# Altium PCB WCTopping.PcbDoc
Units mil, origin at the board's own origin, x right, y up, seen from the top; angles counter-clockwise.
Board outline 6000 x 4000 mil, 2 copper layers (Top Layer, Bottom Layer); 59 components, 76 nets, 281 pads, 0 vias.
Unrouted connection lines stored in the file: 177.
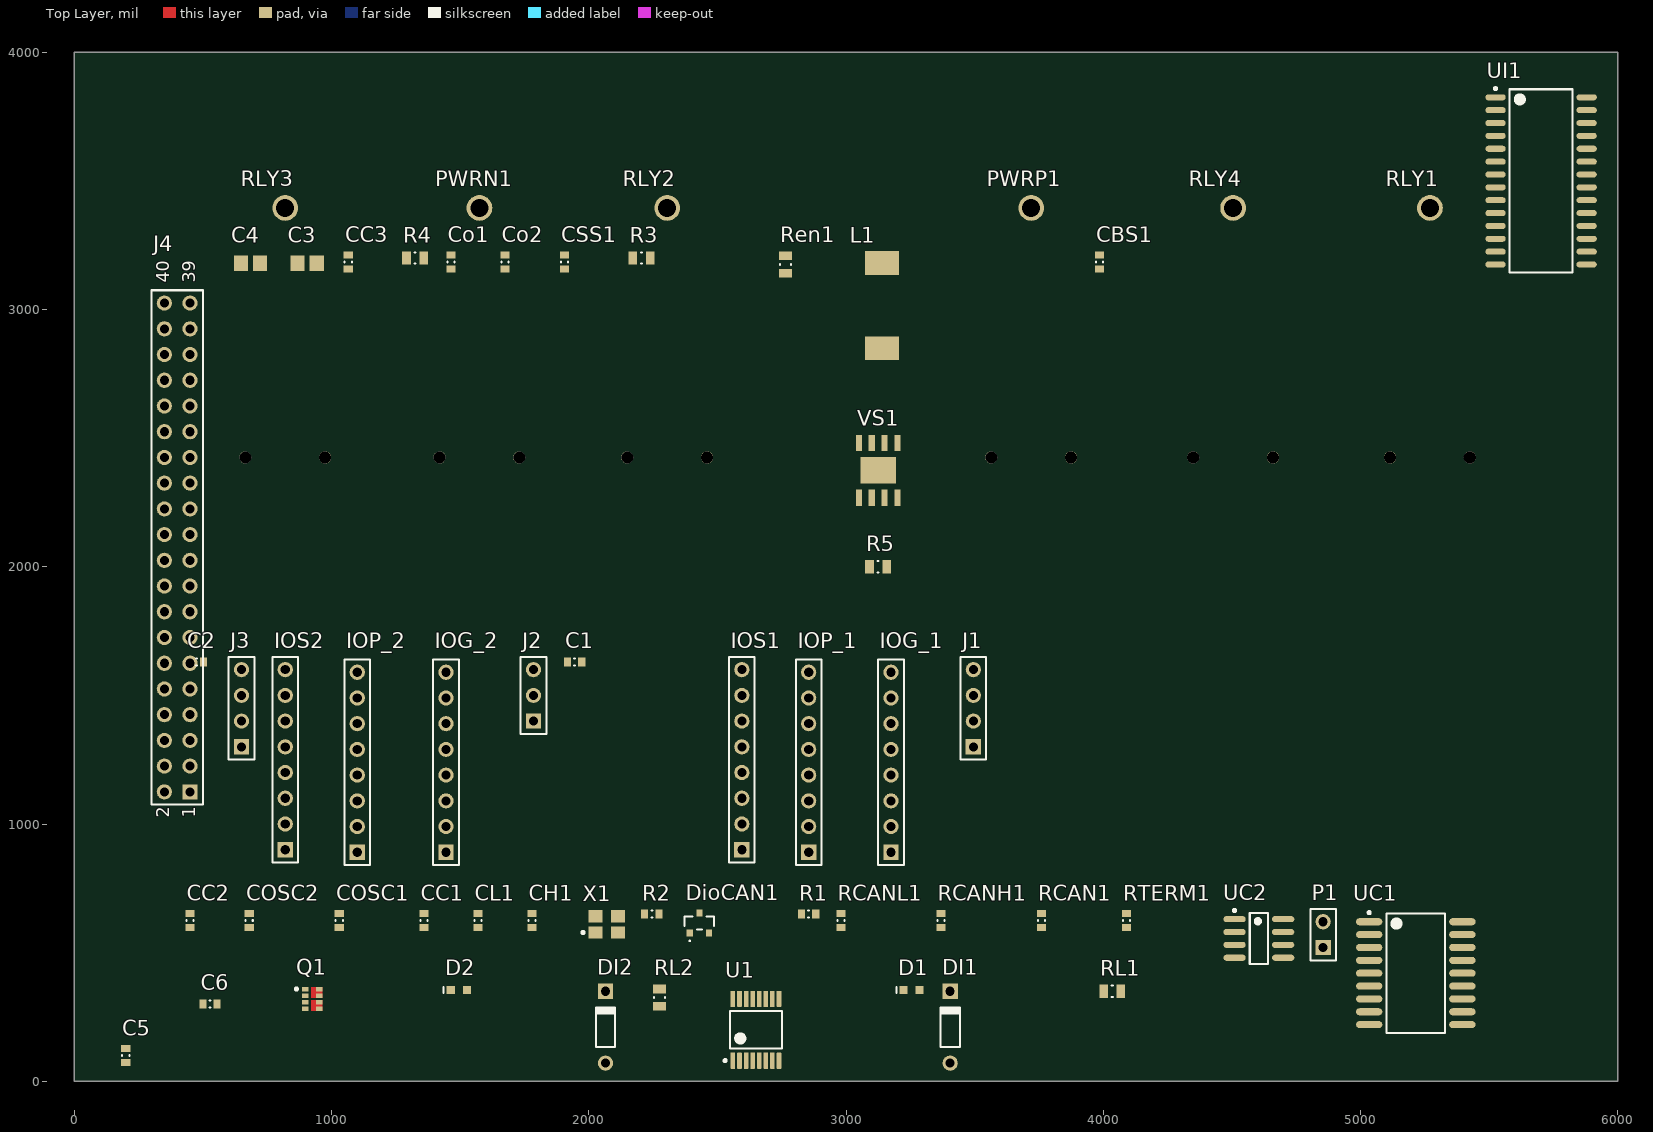
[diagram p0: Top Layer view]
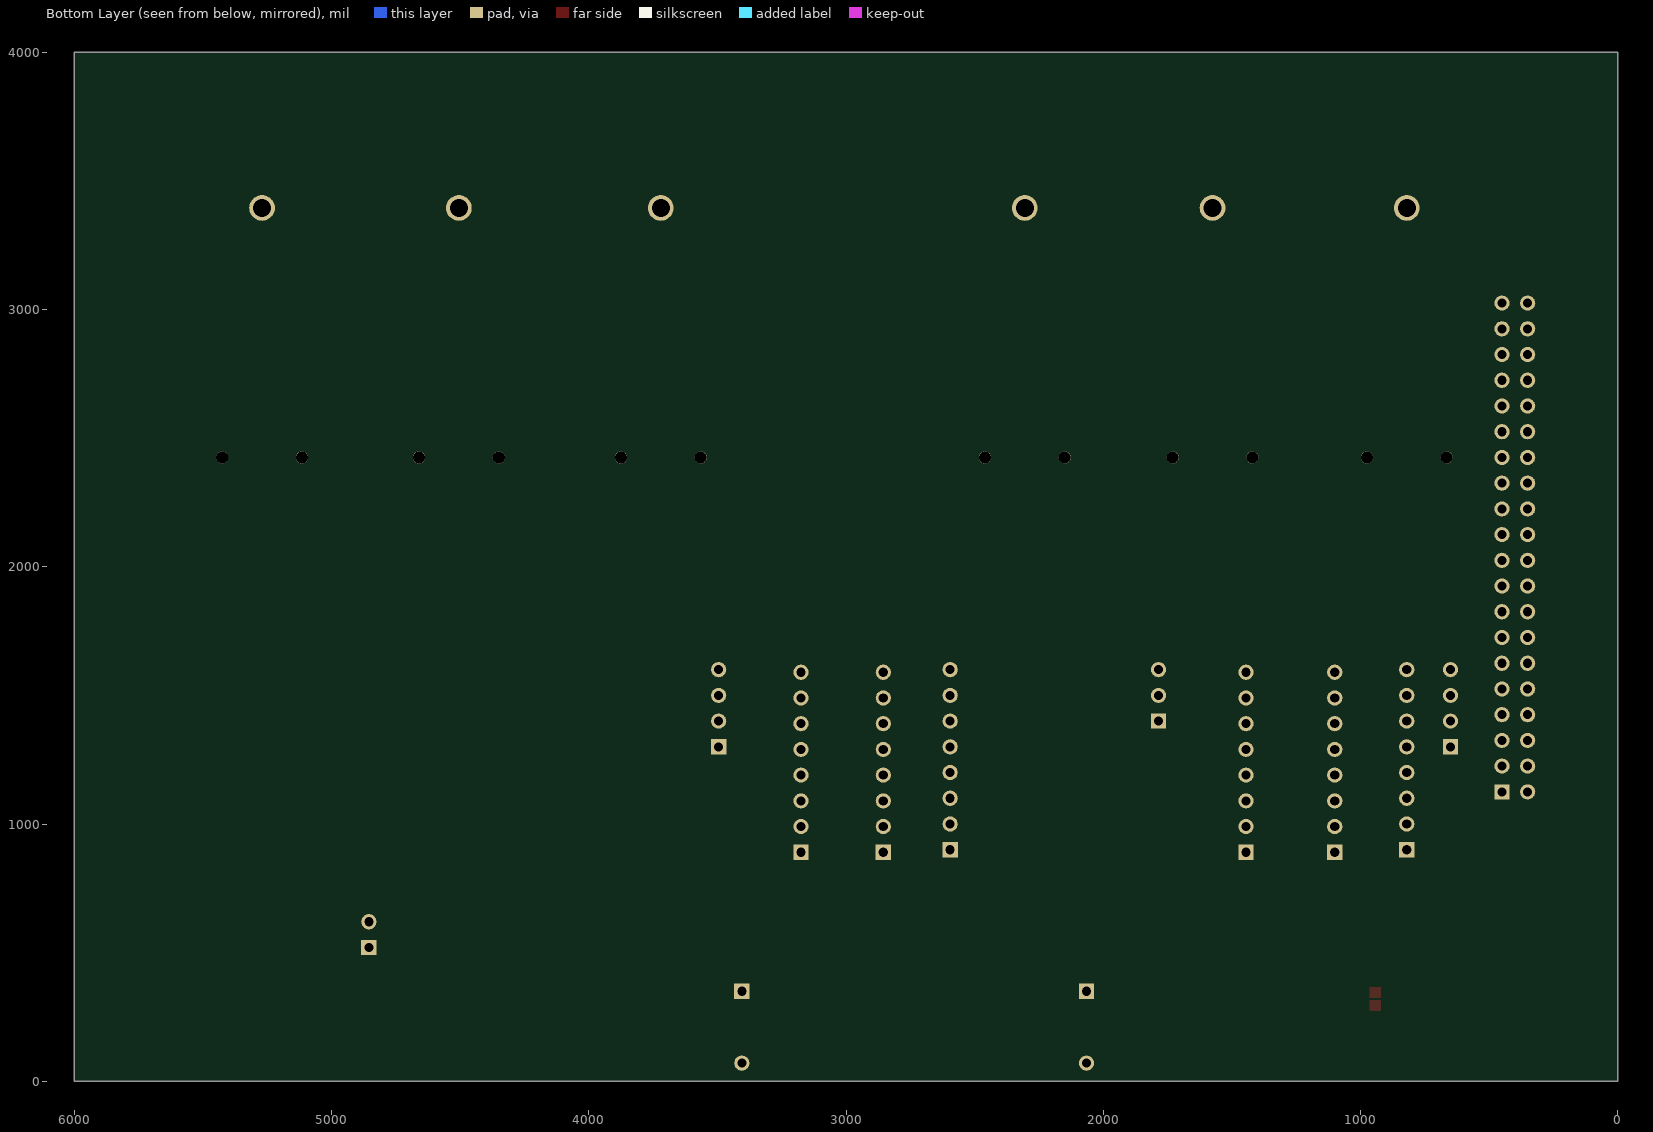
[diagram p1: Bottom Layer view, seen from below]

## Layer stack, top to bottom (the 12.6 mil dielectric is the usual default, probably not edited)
Top Solder: solder mask 0.4, Solder Resist, Dk 3.5
Top Layer: signal copper 1.4
Dielectric 1: dielectric 12.6, FR-4, Dk 4.8
Bottom Layer: signal copper 1.4
Bottom Solder: solder mask 0.4, Solder Resist, Dk 3.5

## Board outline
0,0 6000,0 6000,4000 0,4000

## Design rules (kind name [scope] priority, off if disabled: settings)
Clearance [All] p1: gap=10 ignorepadtopadclearanceinfootprint=FALSE except(0: Arc-Hole Track-Hole SMDPad-Hole THPad-Hole Via-Hole Fill-Hole Poly-Hole Region-Hole Text-Hole)
PolygonConnect [All] p1: connectstyle=Relief reliefconductorwidth=10 reliefentries=4 polygonreliefangle="90 Angle" airgapwidth=10
RoutingVias [All] p1: holewidth=28 width=50 viastyle="Through Hole" minholewidth=28 minwidth=50 maxholewidth=28 maxwidth=50
SolderMaskExpansion [All] p1: expansion=4
Width [All] p1: maxlimit=10 minlimit=10 preferedwidth=10
30 further rules are at their usual default settings.

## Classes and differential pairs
component class CAN_Interface: CC1 CC2 CH1 CL1 COSC1 COSC2 DioCAN1 P1 R1 R2 RCAN1 RCANH1 RCANL1 RTERM1 UC1 UC2 X1
component class Digital_IO: C1 C2 IOG_1 IOG_2 IOP_1 IOP_2 IOS1 IOS2 J1 J2 J3 UI1
component class "Power Supply": C3 C4 CBS1 CC3 Co1 Co2 CSS1 L1 PWRN1 PWRP1 R3 R4 R5 Ren1 VS1
component class Processor_Interface: C5 C6 J4
component class Relay_IO: D1 D2 DI1 DI2 Q1 RL1 RL2 RLY1 RLY2 RLY3 RLY4 U1
net class RELAY[1..2]: RELAY1 RELAY2

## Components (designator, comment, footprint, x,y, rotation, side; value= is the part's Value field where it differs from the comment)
C1 "100nF 50V" 0603C_L 1945,1630 r0 top
C2 "100nF 50V" 0603C_L 475,1630 r0 top
C3 "10µF" CAPC2013X135X45ML10T25 905,3180 r0 top
C4 "10µF" CAPC2013X135X45ML10T25 685,3180 r0 top
C5 "100nF 50V" 0603C_L 200,100 r270 top
C6 "100nF 50V" 0603C_L 527.56,300 r0 top
CBS1 "10000pF 50V 0603" 0603C_L 3985,3185 r90 top
CC1 "0.1uF" 0603C_L 1360,625 r90 top
CC2 "0.1uF" 0603C_L 450,625 r90 top
CC3 "3900pF" 0603C_L 1065,3185 r90 top
CH1 "560pF 25V 0603" 0603C_L 1780,625 r90 top
CL1 "560pF 25V 0603" 0603C_L 1570,625 r90 top
Co1 "22uF" 0603C_L 1465,3185 r90 top
Co2 "22uF" 0603C_L 1675,3185 r90 top
COSC1 "22pF" 0603C_L 1030,625 r90 top
COSC2 "22pF" 0603C_L 680,625 r90 top
CSS1 "100nF 50V" 0603C_L 1905,3185 r90 top
D1 "LED Red" 0603_A 3255,355 r0 top
D2 "LED Red" 0603_A 1495,355 r0 top
DI1 "100V 1A Fast Diode" DO-35 3405,210 r90 top
DI2 "100V 1A Fast Diode" DO-35 2065,210 r90 top
DioCAN1 "100V 1A Fast Diode" SOT23 2430,615 r90 top
IOG_1 "Header 8" HDR1X8 3175,890 r90 top
IOG_2 "Header 8" HDR1X8 1445,890 r90 top
IOP_1 "Header 8" HDR1X8 2855,890 r90 top
IOP_2 "Header 8" HDR1X8 1100,890 r90 top
IOS1 "Header 8" HDR1X8 2595,900 r90 top
IOS2 "Header 8" HDR1X8 820,900 r90 top
J1 "Header 4" HDR1X4 3495,1300 r90 top
J2 "Header 3" HDR1X3 1785,1400 r90 top
J3 "Header 4" HDR1X4 650,1300 r90 top
J4 "Header 20X2" HDR2X20 450,1125 r90 top
L1 "10uH" IND_1 3140,3015 r90 top
P1 "Header 2" HDR1X2 4855,520 r90 top
PWRN1 "BLK_PCB_RHT" Anderson_BLK_RHT_BOT 1575,3395 r90 top
PWRP1 "RED_PCB_RHT" Anderson_Red_RHT_BOT 3720,3395 r90 top
Q1 "NTHD4508NT1" ONSC-CHIPFET-8-1206A-03_S2_V 925,320 r0 top
R1 "10K 0603" 0603_L 2855,650 r0 top
R2 "22K" 0603_L 2245,650 r0 top
R3 "#NAME?" 0805_L 2205,3200 r0 top
R4 "10 kOhms" 0805_L 1325,3200 r0 top
R5 "6.8 kOhms" 0805_L 3125,2000 r180 top
RCAN1 "4.7K" 0603_L 3760,625 r90 top
RCANH1 "100" 0603_L 3370,625 r90 top
RCANL1 "100" 0603_L 2980,625 r90 top
Ren1 "100K 0805" 0805_L 2765,3175 r90 top
RL1 "1K 0805" 0805_L 4035,350 r0 top
RL2 "1K 0805" 0805_L 2275,325 r90 top
RLY1 "Anderson-1Pin RED_PCB_RHT" Anderson_Red_RHT_BOT 5270,3395 r90 top
RLY2 "Anderson-1Pin BLK_PCB_RHT" Anderson_BLK_RHT_BOT 2305,3395 r90 top
RLY3 "Anderson-1Pin RED_PCB_RHT" Anderson_Red_RHT_BOT 820,3395 r90 top
RLY4 "Anderson-1Pin BLK_PCB_RHT" Anderson_BLK_RHT_BOT 4505,3395 r90 top
RTERM1 "130ohm 0603" 0603_L 4090,625 r90 top
U1 "CD40109BPW" PW0016A_M 2650,200 r90 top
UC1 "MCP2515-E/SO" SOIC-SO18_M 5215,420 r0 top
UC2 "MCP2551-E/SN" SOIC-SN8_N 4605,555 r0 top
UI1 "MCP23S17T-E/SO" SOIC-SO28_L 5702.17,3500 r0 top
VS1 "MP2307" SOIC8N_EXP 3125,2375 r0 top
X1 "21C00047-16.000MHz" ITTI-21C00047-16.000MHz-4_V 2070,610 r0 top

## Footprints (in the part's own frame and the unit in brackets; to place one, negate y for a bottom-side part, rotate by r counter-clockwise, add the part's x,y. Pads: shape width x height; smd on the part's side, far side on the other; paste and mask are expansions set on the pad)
0603_A [mm] "Chip LED, 2-Leads, Body 1.6x0.8mm, IPC Medium Density"
  rect 0.8x0.8 smd: 1(-0.8,0) 2(0.8,0)
  silkscreen extent -1.5,-0.3 -1.5,0.3, body extent -0.8,-0.4 0.8,0.4, height 0.7
0603_L [mm]
  rect 0.7x0.9 smd: 1(-0.7,0) 2(0.7,0)
  silkscreen extent -0.05,-0.35 0.05,0.35, body extent -0.85,-0.47 0.85,0.47, height 0.6
0603C_L [mm]
  rect 0.7x0.9 smd: 1(-0.7,0) 2(0.7,0)
  silkscreen extent -0.05,-0.35 0.05,0.35, body extent -0.87,-0.47 0.88,0.48, height 1
0805_L [mm]
  rect 0.85x1.3 smd: 1(-0.85,0) 2(0.85,0)
  silkscreen extent -0.05,-0.55 0.05,0.55, body extent -1.1,-0.67 1.1,0.68, height 0.7
Anderson_BLK_RHT_BOT [mil]
  round 100 hole 70: 1(0,0)
  round 47 hole 47 unplated: MH(-970,-155) MH(-970,155)
  body extent -1360,-155 25,155, height 310
Anderson_Red_RHT_BOT [mil]
  round 100 hole 70: 1(0,0)
  round 47 hole 47 unplated: MH(-970,-155) MH(-970,155)
  body extent -1360,-155 25,155, height 310
CAPC2013X135X45ML10T25 [mm] "Chip Capacitor, 2-Leads, Body 2.00x1.25mm, IPC Low Density"
  rect 1.4x1.5 smd: 1(-0.95,0) 2(0.95,0)
  body extent -1.05,-0.67 1.05,0.67, height 1.35
DO-35 [mm] "Diode, Axial; Body 3.8 x 1.9 mm (LxDia. max), Lead Dia. 0.53 mm (max)"
  round 1.5 hole 0.9: 1(-3.55,0)
  rect 1.5x1.5 hole 0.9: 2(3.55,0)
  silkscreen extent -1.95,-0.95 2.05,0.95
HDR1X2 [mm] "Connector; Header; 2 Position"
  rect 1.5x1.5 hole 0.9: 1(0,0)
  round 1.5 hole 0.9: 2(2.54,0)
  silkscreen extent -1.27,-1.27 3.81,1.27
HDR1X3 [mm] "Connector; Header; 3 Position"
  rect 1.5x1.5 hole 0.9: 1(0,0)
  round 1.5 hole 0.9: 2(2.54,0) 3(5.08,0)
  silkscreen extent -1.27,-1.27 6.35,1.27
HDR1X4 [mm] "Connector; Header; 4 Position"
  rect 1.5x1.5 hole 0.9: 1(0,0)
  round 1.5 hole 0.9: 2(2.54,0) 3(5.08,0) 4(7.62,0)
  silkscreen extent -1.27,-1.27 8.89,1.27
HDR1X8 [mm] "Connector; Header; 8 Position"
  rect 1.5x1.5 hole 0.9: 1(0,0)
  round 1.5 hole 0.9: 2(2.54,0) 3(5.08,0) 4(7.62,0) 5(10.16,0) 6(12.7,0) 7(15.24,0) 8(17.78,0)
  silkscreen extent -1.27,-1.27 19.05,1.27
HDR2X20 [mm] "Connector; Header; 20x2 Position"
  rect 1.5x1.5 hole 0.9: 1(0,0)
  round 1.5 hole 0.9: 2(0,2.54) 3(2.54,0) 4(2.54,2.54) 5(5.08,0) 6(5.08,2.54) 7(7.62,0) 8(7.62,2.54) 9(10.16,0) 10(10.16,2.54) 11(12.7,0) 12(12.7,2.54) 13(15.24,0) 14(15.24,2.54) 15(17.78,0) 16(17.78,2.54) 17(20.32,0) 18(20.32,2.54) 19(22.86,0) 20(22.86,2.54) 21(25.4,0) 22(25.4,2.54) 23(27.94,0) 24(27.94,2.54) 25(30.48,0) 26(30.48,2.54) 27(33.02,0) 28(33.02,2.54) 29(35.56,0) 30(35.56,2.54) 31(38.1,0) 32(38.1,2.54) 33(40.64,0) 34(40.64,2.54) 35(43.18,0) 36(43.18,2.54) 37(45.72,0) 38(45.72,2.54) 39(48.26,0) 40(48.26,2.54)
  silkscreen extent -1.27,-1.27 49.53,3.81
IND_1 [mil]
  rect 92.52x134 smd: 1(-165.5,0) 2(165.5,0)
  body extent -142,-127 142,135, height 118
ITTI-21C00047-16.000MHz-4_V [mm] "Hand Drawn, 4-Leads, Body 3.2x2.5 mm"
  rect 1.4x1.2 smd: 1(-1.1,-0.8) 2(1.1,-0.8) 3(1.1,0.8) 4(-1.1,0.8)
  silkscreen extent -2.47,-0.92 -2.23,-0.68, body extent -1.6,-1.25 1.6,1.25, height 0.9
ONSC-CHIPFET-8-1206A-03_S2_V [mil] "SON, 8-Leads, Body 3.025x1.625mm, Pitch 0.635mm"
  rect 25.98x17.99 smd: 1(-27.01,37.5) 2(-27.01,12.5) 3(-27.01,-12.5) 4(-27.01,-37.5) 5(27.01,-37.5) 6(27.01,-12.5) 7(27.01,12.5) 8(27.01,37.5)
  Top Layer region: -4.02,3.5 40,3.5 40,46.5 -4.02,46.5
  Top Layer region: -4.02,-46.5 40,-46.5 40,-3.5 -4.02,-3.5
  silkscreen extent -67,33 -57,43, body extent -32,-60 32,60, height 43
PW0016A_M [mm] "SOP, 16-Leads, Body 5.1x4.5mm, Pitch 0.65mm, IPC Low Density"
  rrect22% 1.6x0.45 smd: 1(-3.05,2.275) 2(-3.05,1.625) 3(-3.05,0.975) 4(-3.05,0.325) 5(-3.05,-0.325) 6(-3.05,-0.975) 7(-3.05,-1.625) 8(-3.05,-2.275) 9(3.05,-2.275) 10(3.05,-1.625) 11(3.05,-0.975) 12(3.05,-0.325) 13(3.05,0.325) 14(3.05,0.975) 15(3.05,1.625) 16(3.05,2.275)
  silkscreen extent -3.17,-2.55 1.85,3.17, body extent -3.21,-2.5 3.21,2.5, height 1
SOIC8N_EXP [mil]
  rect 24x63 smd: 1(-75,-106.5) 2(-25,-106.5) 3(25,-106.5) 4(75,-106.5) 5(75,106.5) 6(25,106.5) 7(-25,106.5) 8(-75,106.5)
  rect 138x103 smd: EP(0,0)
SOIC-SN8_N [mm] "SOIC, 8-Leads, Body 4.9x3.9mm, Pitch 1.27mm, IPC Medium Density"
  oval 2.2x0.6 smd: 1(-2.4,1.905) 2(-2.4,0.635) 3(-2.4,-0.635) 4(-2.4,-1.905) 5(2.4,-1.905) 6(2.4,-0.635) 7(2.4,0.635) 8(2.4,1.905)
  silkscreen extent -2.52,-2.5 0.9,2.88, body extent -2,-2.5 2,2.5, height 1.75
SOIC-SO18_M [mm] "SOIC, 18-Leads, Body 11.6x7.5mm, Pitch 1.27mm, IPC Low Density"
  oval 2.6x0.7 smd: 1(-4.6,5.08) 2(-4.6,3.81) 3(-4.6,2.54) 4(-4.6,1.27) 5(-4.6,0) 6(-4.6,-1.27) 7(-4.6,-2.54) 8(-4.6,-3.81) 9(-4.6,-5.08) 10(4.6,-5.08) 11(4.6,-3.81) 12(4.6,-2.54) 13(4.6,-1.27) 14(4.6,0) 15(4.6,1.27) 16(4.6,2.54) 17(4.6,3.81) 18(4.6,5.08)
  silkscreen extent -4.72,-5.9 2.9,6.1, body extent -3.8,-5.87 3.8,5.87, height 2.65
SOIC-SO28_L [mm] "SOIC, 28-Leads, Body 17.9x7.5mm, Pitch 1.27mm, IPC High Density"
  oval 2x0.6 smd: 1(-4.5,8.255) 2(-4.5,6.985) 3(-4.5,5.715) 4(-4.5,4.445) 5(-4.5,3.175) 6(-4.5,1.905) 7(-4.5,0.635) 8(-4.5,-0.635) 9(-4.5,-1.905) 10(-4.5,-3.175) 11(-4.5,-4.445) 12(-4.5,-5.715) 13(-4.5,-6.985) 14(-4.5,-8.255) 15(4.5,-8.255) 16(4.5,-6.985) 17(4.5,-5.715) 18(4.5,-4.445) 19(4.5,-3.175) 20(4.5,-1.905) 21(4.5,-0.635) 22(4.5,0.635) 23(4.5,1.905) 24(4.5,3.175) 25(4.5,4.445) 26(4.5,5.715) 27(4.5,6.985) 28(4.5,8.255)
  silkscreen extent -4.62,-9.05 3.1,9.23, body extent -3.8,-9.05 3.8,9.05, height 2.65
SOT23 [mm]
  rect 0.7x0.6 smd paste-0.05: 1(-1,0.95) 2(-1,-0.95) 3(1,0)
  silkscreen extent -1.79,-1.45 0.65,1.45, body extent -1.3,-1.5 1.3,1.5, height 1.1

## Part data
C1 C2 C5 C6 CSS1: library part Cap100nF_50V_0603, Capacitance=0.10µF, Manufacturer=Yageo, Manufacturer Part Number=CC0603ZRY5V9BB104, Operating Temperature="-30°C ~ 85°C", Package / Case="0603 (1608 Metric)", Ratings=-, Supplier Part Number 1=311-1343-1-ND, Temperature Coefficient="Y5V (F)", Tolerance="-20%, +80%", Voltage - Rated=50V
C3 C4: library part CMP-2007-03541-1, Manufacturer=Murata, Manufacturer Part Number=GRM21BR61E106KA73L, Operating Temperature="-55°C ~ 85°C", Package / Case="0805 (2012 Metric)", Ratings=-, Standard Package=1, Supplier Part Number 1=490-5523-1-ND, Temperature Coefficient=X5R, Tolerance=±10%, Voltage - Rated=25V
CBS1: library part Cap10000pF_50V_0603, Capacitance=10000pF, Manufacturer=Yageo, Manufacturer Part Number=CC0603KRX7R9BB103, Operating Temperature="-55°C ~ 125°C", Package / Case="0603 (1608 Metric)", Ratings=-, Standard Package=1, Supplier Part Number 1=311-1085-1-ND, Temperature Coefficient=X7R, Tolerance=±10%, Voltage - Rated=50V
CC1 CC2: library part Cap10uF_25V_0603
CC3: library part Cap_0603_1, Case Style="Ceramic Chip", Manufacturer=Murata, Manufacturer Part Number=GRM188R71E392KA01D, Operating Temp Range="-55C to 125C", Package / Case=0603, Supplier Part Number 1=490-11525-1-ND, Temp Coeff (Dielectric)=X7R, Tolerance (+ or -)=10%, Voltage=25VDC
CH1 CL1: library part Cap10uF_25V_0603, Capacitance=10µF, Manufacturer="Taiyo Yuden", Manufacturer Part Number=TMK316F106ZL-T, Operating Temperature="-30°C ~ 85°C", Package / Case="1206 (3216 Metric)", Ratings=-, Standard Package=1, Supplier Part Number 1=587-1353-1-ND, Temperature Coefficient="Y5V (F)", Tolerance="-20%, +80%", Voltage - Rated=25V
Co1 Co2: library part Cap_0603_1, Case Style="Ceramic Chip", Manufacturer=Murata, Manufacturer Part Number=GRM188R60J226MEA0D, Operating Temp Range="-55C to 125C", Package / Case=0603, Supplier Part Number 1=490-7611-1-ND, Temp Coeff (Dielectric)=X5R, Tolerance (+ or -)=20%, Voltage=6.3VDC
COSC1 COSC2: library part Cap100nF_50V_0603, Capacitance=22, Case/Package=0603, Case Code (Metric)=1608, Manufacturer=Murata, Manufacturer Part Number=GRM1885C1H220JA01D, Max Operating Temperature=125, Min Operating Temperature=-55, Package Quantity=1, Supplier Part Number 1=490-1411-1-ND, Tolerance=5, Type (Capacitors)=C0G, Voltage Rating=50
D1 D2: library part LED_Red0603, "SMD mono-color Chip LED, WL-SMCW, Red", Color=Red, Current - Test=20mA, Lens Color=Colorless, Manufacturer="Wurth Electronics Inc", Manufacturer Part Number=150060RS75000, Millicandela Rating=250mcd, Package / Case="0603 (1608 Metric)", Supplier Device Package=0603, Supplier Part Number 1=732-4978-1-ND, Voltage - Forward (Vf) (Typ)=2V
DI1 DI2: library part "Diode 1N4148", "High Conductance Fast Diode", Diode Case Style=DO-204AL, Forward Current If(AV)=1A, Forward Surge Current Ifsm Max=35A, Forward Voltage VF Max=1.25V, Manufacturer="ON Semiconductor", Manufacturer Part Number=MUR110RLG, Operating Temperature Max=175°C, Repetitive Reverse Voltage Vrrm Max=100V, Supplier Part Number 1=MUR110RLGOSCT-ND
DioCAN1: library part PESD1CAN, "High Conductance Fast Diode", Diode Case Style=DO-204AL, Forward Current If(AV)=1A, Forward Surge Current Ifsm Max=35A, Forward Voltage VF Max=1.25V, Manufacturer="ON Semiconductor", Manufacturer Part Number=MUR110RLG, Operating Temperature Max=175°C, Repetitive Reverse Voltage Vrrm Max=100V, Supplier Part Number 1=MUR110RLGOSCT-ND
IOG_1 IOG_2 IOP_1 IOP_2 IOS1 IOS2: "Header, 8-Pin"
J1 J3: "Header, 4-Pin"
J2: "Header, 3-Pin"
J4: "Header, 20-Pin, Dual row"
L1: library part Inductor, "Inductor", Inductance="10 uH", Manufacturer=Abracon, Manufacturer Part Number=ASPI-0630LR-100M-T15, Maximum DC Current="4 A", Maximum DC Resistance="68 mOhm", Package/Case=2826, Supplier Part Number 1=ASPI-0630LR-100M-T15CT-ND, Tolerance="20 %"
P1: "Header, 2-Pin"
PWRN1: library part "Anderson-1Pin BLK_PCB_RHT", "1 pin Anderson", Current Rating="25 A", Manufacturer="Anderson Power Products (APP)", Manufacturer Part Number="1377G1, 1377G2, 1327-BK,137G6-BK", Supplier Part Number 1=879-1377G1, Voltage Rating="600 V"
PWRP1: library part "Anderson-1Pin RED_PCB_RHT", "1 pin Anderson", Current Rating="25 A", Manufacturer="Anderson Power Products (APP)", Manufacturer Part Number="1377G1, 1377G2, 1327-BK,137G6-BK", Supplier Part Number 1=879-1377G1, Voltage Rating="600 V"
Q1: "Power MOSFET, 20 V, 4.1 A, Dual N-Channel, 8-Pin CHIPFET, Tape and Reel", Current - Continuous Drain (Id) @ 25°C=3A, Drain to Source Voltage (Vdss)=20V, Input Capacitance (Ciss) @ Vds="180pF @ 10V", Manufacturer="On Semiconductor", Manufacturer Part Number=NTHD4508NT1G, Operating Temperature="-55°C ~ 150°C (TJ)", Package / Case="8-SMD, Flat Lead", Package Type=ChipFET-8, Power - Max=1.13W, Supplier Device Package=ChipFET™, Supplier Part Number 1=NTHD4508NT1GOSCT-ND
R1: library part Res4K99_0603, Manufacturer=Yageo, Manufacturer Part Number=RT0603DRD074K99L, Operating Temperature="-55°C ~ 155°C", Package / Case="0603 (1608 Metric)", Power (Watts)="0.1W, 1/10W", Resistance (Ohms)=10K, Supplier Device Package=0603, Supplier Part Number 1=311-10KDCT-ND, Temperature Coefficient=±25ppm/°C, Tolerance=±0.5%
R2: library part Res_0603, Case Code - in=0603, Case Code - mm=1608, Manufacturer=Yageo, Manufacturer Part Number=RT0603DRD0722KL, Operating Temperature Range="- 55 C to + 125 C", Package / Case="0603 (1608 metric)", Power Rating="100 mW", Resistance="22 kOhms", Supplier Part Number 1=311-22KDDKR-ND, Temperature Coefficient="25 PPM / C", Tolerance="0.5 %", Voltage Rating="75 V"
R3: library part Res_0805, Manufacturer=Yageo, Manufacturer Part Number=RC0805FR-0744K2L, Operating Temperature="-55°C ~ 155°C", Package / Case="0805 (2012 Metric)", Power (Watts)="0.125W, 1/8W", Resistance (Ohms)=44.2k, Standard Package=1, Supplier Device Package=0805, Supplier Part Number 1=311-44.2KCRCT-ND, Temperature Coefficient=±100ppm/°C, Tolerance=±1%
R4: library part Res_0805, Case Code - in=0805, Case Code - mm=2012, Manufacturer=Yageo, Manufacturer Part Number=RC0805FR-0710KL, Operating Temperature Range="- 55 C to + 155 C", Power Rating="125 mW (1/8 W)", Supplier Part Number 1=311-10.0KCRCT-ND, Temperature Coefficient="100 PPM / C", Tolerance="1 %", Voltage Rating="150 V"
R5: library part Res_0805, Case Code - in=0805, Case Code - mm=2012, Manufacturer=Yageo, Manufacturer Part Number=RC0805JR-076K8L, Operating Temperature Range="- 55 C to + 155 C", Power Rating="125 mW (1/8 W)", Supplier Part Number 1=311-6.8KARCT-ND, Temperature Coefficient="100 PPM / C", Tolerance="5 %", Voltage Rating="150 V"
RCAN1: library part Res4K99_0603, Manufacturer=Yageo, Manufacturer Part Number=RT0603DRD074K99L, Operating Temperature="-55°C ~ 155°C", Package / Case="0603 (1608 Metric)", Power (Watts)="0.1W, 1/10W", Resistance (Ohms)=4.99k, Supplier Device Package=0603, Supplier Part Number 1=311-4.99KDCT-ND, Temperature Coefficient=±25ppm/°C, Tolerance=±0.5%
RCANH1 RCANL1: library part Res330_0603, Manufacturer=Yageo, Manufacturer Part Number=RC0603JR-07330RL, Operating Temperature="-55°C ~ 155°C", Package / Case="0603 (1608 Metric)", Power (Watts)="0.1W, 1/10W", Resistance (Ohms)=330, Supplier Device Package=0603, Supplier Part Number 1=311-330GRCT-ND, Temperature Coefficient=±100ppm/°C, Tolerance=±5%
Ren1: library part Res100K_080, Manufacturer="Panasonic / Panasonic ECG", Manufacturer Part Number=ERJ-6GEYJ104V, Rated Power="0.125 W", Resistance="100 kO", Supplier Part Number 1=P100KACT-ND, Temp Coefficient="±200 ppm/°C", Tolerance (%)="±5 %"
RL1 RL2: library part Res1K_0805, Manufacturer="Panasonic Electronic Components", Manufacturer Part Number=ERJ-6GEYJ102V, Operating Temperature="-55°C ~ 155°C", Package / Case="0805 (2012 Metric)", Power (Watts)="0.125W, 1/8W", Resistance (Ohms)=1k, Supplier Device Package=0805, Supplier Part Number 1=P1.0KACT-ND, Temperature Coefficient=±200ppm/°C, Tolerance=±5%
RLY1 RLY2 RLY3 RLY4: "1 pin Anderson", Current Rating="25 A", Manufacturer="Anderson Power Products (APP)", Manufacturer Part Number="1377G1, 1377G2, 1327-BK,137G6-BK", Supplier Part Number 1=879-1377G2, Voltage Rating="600 V"
RTERM1: library part Res330_0603
U1: library part CMP-1527-00010-2, "CMOS Quad Low-to-High Voltage Level Shifter, 3 to 18 V, -55 to 125 degC, 16-Pin TSSOP (PW16), RoHS, Tube", Manufacturer="Texas Instruments", Manufacturer Part Number=CD40109BPWR, Operating Temperature="-55°C ~ 125°C", Package / Case="16-TSSOP (0.173\", 4.40mm Width)", Package Reference=PW0016A, Standard Package=1, Supplier Device Package=16-TSSOP, Supplier Part Number 1=296-12163-6-ND, Temperature Range="-55 to 125 degC", Voltage - Supply="3 V ~ 18 V"
UC1: library part CMP-0186-00035-2, "Stand-Alone CAN Controller With SPI Interface, 18-Pin SOIC, Extended Temperature"
UC2: library part CMP-0186-00038-2, "High-Speed CAN Transceiver, 8-Pin SOIC, Extended Temperature"
UI1: library part CMP-0186-00131-2, "16-Bit I/O Expander with Serial Interface, 28-Pin SOIC, Extended Temperature, Tape and Reel"
VS1: Input Voltage MAX="23 V", Input Voltage MIN="4.75 V", Manufacturer="Monolithic Power Systems (MPS)", Manufacturer Part Number=MP2307DN-LF-Z, Maximum Operating Temperature="+ 85 C", Minimum Operating Temperature="- 40 C", Output Current="3 A", Output Voltage="0.925 V to 20 V", Package / Case="SOIC-8 EP", Supplier Part Number 1=946-MP2307DNLFZ, Supply Current="1.3 mA", Switching Frequency="340 kHz"
X1: library part CMP-0464-00001-2, "Crystal, 16 MHz, -30 to 85 degC, 3.2 x 2.5 x 0.9 mm SMD", Frequency Tolerance="+/-20 ppm", Load Capacitance="10 pF", Manufacturer=ITTI, Nominal Frequency="16 MHz", Operating Temperature="-30 to 85 degC"

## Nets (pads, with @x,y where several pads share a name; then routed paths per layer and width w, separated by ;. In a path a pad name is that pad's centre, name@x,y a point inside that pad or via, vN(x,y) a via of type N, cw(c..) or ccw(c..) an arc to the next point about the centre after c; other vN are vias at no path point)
3V3: C1.2 C6.2 CC2.2 J1.3 J3.1 J4.1 J4.17 U1.1 U1.2 U1.7 UC1.18
5V: C5.2 CC1.2 Co1.2 Co2.2 IOP_1.1 IOP_1.2 IOP_1.3 IOP_1.4 IOP_1.5 IOP_1.6 IOP_1.7 IOP_1.8 IOP_2.1 IOP_2.2 IOP_2.3 IOP_2.4 IOP_2.5 IOP_2.6 IOP_2.7 IOP_2.8 J4.2 J4.4 L1.2 R3.1 UC2.3 UI1.9
12V: C3.2 C4.2 DI1.2 DI2.2 PWRP1.1 Ren1.1 RL1.2 RL2.2 RLY1.1 RLY3.1 U1.16 VS1.2
\IO_RESET: J4.40 UC1.17 UI1.18
AUX_CL: J2.1
AUX_DA: J2.3
C\S\: J3.3 J4.24
CAN_RXD: R1.2 R2.2 UC1.2
CAN_TXD: UC1.1 UC2.1
CANH: DioCAN1.1 P1.1 RCANH1.2 RTERM1.2 UC2.7
CANL: DioCAN1.2 P1.2 RCANL1.2 RTERM1.1 UC2.6
FSYNC: J2.2
GND: C1.1 C2.1 C3.1 C4.1 C5.1 C6.1 CC1.1 CC2.1 CH1.2 CL1.1 Co1.1 Co2.1 COSC1.1 COSC2.2 CSS1.1 DioCAN1.3 IOG_1.1 IOG_1.2 IOG_1.3 IOG_1.4 IOG_1.5 IOG_1.6 IOG_1.7 IOG_1.8 IOG_2.1 IOG_2.2 IOG_2.3 IOG_2.4 IOG_2.5 IOG_2.6 IOG_2.7 IOG_2.8 J1.4 J3.2 J4.6 J4.9 J4.14 J4.20 J4.25 J4.30 J4.34 J4.39 PWRN1.1 Q1.1 Q1.3 R2.1 R4.2 R5.1 RCAN1.1 U1.8 U1.9 U1.15 UC1.9 UC2.2 UI1.10 UI1.15 UI1.16 UI1.17 VS1.4 X1.2 X1.4
GPIO2: J1.2 J4.3
GPIO3: J1.1 J4.5
GPIO4: J4.7 UC1.16 UI1.11
GPIO7: J4.26
GPIO12: J4.32 UI1.20
GPIO13: J4.33
GPIO14: J4.8
GPIO15: J4.10
GPIO16: J4.36 UI1.19
GPIO17: J4.11
GPIO18: J4.12
GPIO19: J4.35
GPIO20: J4.38 UC1.12
GPIO22: J4.15
GPIO23: J4.16
GPIO24: J4.18
GPIO25: J4.22
GPIO26: J4.37
GPIO27: J4.13
ID_SC: J4.28
ID_SD: J4.27
INT: J3.4
IOA_0: IOS1.1 UI1.21
IOA_1: IOS1.2 UI1.22
IOA_2: IOS1.3 UI1.23
IOA_3: IOS1.4 UI1.24
IOA_4: IOS1.5 UI1.25
IOA_5: IOS1.6 UI1.26
IOA_6: IOS1.7 UI1.27
IOA_7: IOS1.8 UI1.28
IOB_0: IOS2.1 UI1.1
IOB_1: IOS2.2 UI1.2
IOB_2: IOS2.3 UI1.3
IOB_3: IOS2.4 UI1.4
IOB_4: IOS2.5 UI1.5
IOB_5: IOS2.6 UI1.6
IOB_6: IOS2.7 UI1.7
IOB_7: IOS2.8 UI1.8
NetCBS1_1: CBS1.1 L1.1 VS1.3
NetCBS1_2: CBS1.2 VS1.1
NetCC3_1: CC3.1 R5.2
NetCC3_2: CC3.2 VS1.6
NetCH1_1: CH1.1 RCANH1.1
NetCL1_2: CL1.2 RCANL1.1
NetCOSC1_2: COSC1.2 UC1.7 X1.3
NetCOSC2_1: COSC2.1 UC1.8 X1.1
NetCSS1_2: CSS1.2 VS1.8
NetD1_1: D1.1 DI1.1 Q1.5 Q1.6 RLY2.1
NetD1_2: D1.2 RL1.1
NetD2_1: D2.1 DI2.1 Q1.7 Q1.8 RLY4.1
NetD2_2: D2.2 RL2.1
NetQ1_2: Q1.2 U1.5
NetQ1_4: Q1.4 U1.4
NetR1_1: R1.1 UC2.4
NetR3_2: R3.2 R4.1 VS1.5
NetRCAN1_2: RCAN1.2 UC2.8
NetRen1_2: Ren1.2 VS1.7
RELAY1: J4.29 U1.3
RELAY2: J4.31 U1.6
SPI_MISO: J4.21 UI1.14
SPI_MOSI: J4.19 UC1.14
SPI_MOSIA: UC1.15 UI1.13
SPI_SCLK: J4.23 UC1.13 UI1.12
pads on no net: C2.2 PWRN1.MH PWRP1.MH RLY1.MH RLY2.MH RLY3.MH RLY4.MH U1.10 U1.11 U1.12 U1.13 U1.14 UC1.3 UC1.4 UC1.5 UC1.6 UC1.10 UC1.11 UC2.5 VS1.EP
